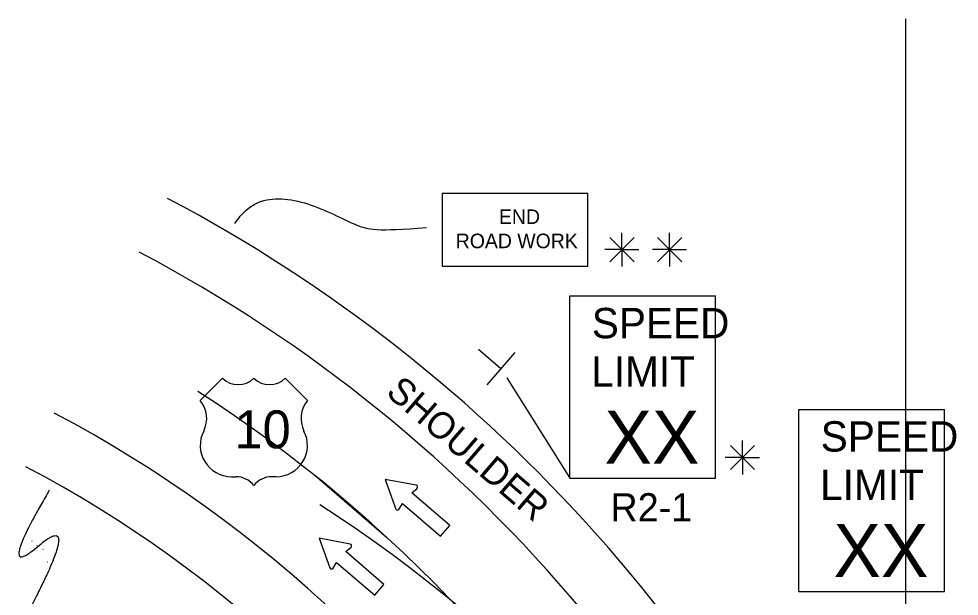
# Model space of a CAD drawing. Extents: x 16729 to 18464, y 5737 to 6974.
# Drawn here: x 16747 to 16994.8, y 6821.9 to 6974.1 of the extents above; entities that cross this region are included whole.
import ezdxf

# ---------------------------------------------------------------- set-up
doc = ezdxf.new("R2010")
doc.units = 0
for name, color, linetype in [('ALI_LEGAL_EX', 7, 'Continuous'), ('MT_SCRATCH_LEVEL_E', 7, 'Continuous'), ('PAVT_EDGE_EX', 7, 'Continuous'), ('TRAFFIC_SIGNS_PR', 7, 'Continuous'), ('TYPICAL_EX', 7, 'Continuous'), ('TYPICAL_TEXT_DIMEN_PR', 7, 'Continuous')]:
    doc.layers.add(name, color=color, linetype=linetype)

msp = doc.modelspace()

# ---------------------------------------------------------------- linework, layer by layer
at = {"layer": 'ALI_LEGAL_EX'}
for p, q in [((16980.68, 6974.12), (16980.68, 6155.98)), ((16980.68, 6891.53), (16980.68, 6027.61))]:
    msp.add_line(p, q, dxfattribs=at)
msp.add_lwpolyline([(16843.92, 6837.36), (16824.97, 6853.66)], dxfattribs=at)
for centre in [(16597.51, 6569.52), (16629.65, 6539.64)]:
    msp.add_arc(centre, 364, 0, 57.2958, dxfattribs=at)
at = {"layer": 'MT_SCRATCH_LEVEL_E'}
for p, q in [((16851.73, 6851.09), (16843.54, 6852.67)), ((16843.54, 6852.67), (16846.35, 6844.83)), ((16850.54, 6849.14), (16851.94, 6850.28)), ((16860.59, 6840.5), (16850.54, 6849.14)), ((16847.18, 6844.75), (16848.1, 6846.31)), ((16848.1, 6846.31), (16858.15, 6837.66)), ((16858.15, 6837.66), (16860.59, 6840.5)), ((16834.35, 6835.57), (16826.16, 6837.15)), ((16826.16, 6837.15), (16828.97, 6829.31)), ((16833.16, 6833.62), (16834.56, 6834.76)), ((16843.21, 6824.97), (16833.16, 6833.62)), ((16829.8, 6829.23), (16830.72, 6830.78)), ((16830.72, 6830.78), (16840.77, 6822.14)), ((16840.77, 6822.14), (16843.21, 6824.97))]:
    msp.add_line(p, q, dxfattribs=at)
for centre, start, end in [((16851.63, 6850.64), 309.3361, 79.073), ((16846.78, 6845), 199.7248, 329.2637), ((16834.25, 6835.11), 309.3361, 79.073), ((16829.4, 6829.47), 199.7248, 329.2637)]:
    msp.add_arc(centre, 0.463, start, end, dxfattribs=at)
at = {"layer": 'PAVT_EDGE_EX'}
for centre, radius, start, end in [((16597.51, 6569.52), 404, 21.0961, 62.1564), ((16597.51, 6569.52), 388, 17.5132, 62.1564), ((17325.51, 6569.52), 380, 123.7854, 157.5011), ((17325.51, 6569.52), 364, 123.7854, 165.0045), ((16597.51, 6569.52), 340, 0, 62.1564), ((16597.51, 6569.52), 324, 0, 62.1564)]:
    msp.add_arc(centre, radius, start, end, dxfattribs=at)
at = {"layer": 'TRAFFIC_SIGNS_PR'}
for p, q in [((16892.23, 6901.02), (16930.63, 6901.02)), ((16892.23, 6853.02), (16892.23, 6901.02)), ((16930.63, 6853.02), (16930.63, 6901.02)), ((16952.57, 6871.13), (16990.97, 6871.13)), ((16952.57, 6823.13), (16952.57, 6871.13)), ((16990.97, 6823.13), (16990.97, 6871.13)), ((16892.23, 6853.02), (16930.63, 6853.02)), ((16952.57, 6823.13), (16990.97, 6823.13))]:
    msp.add_line(p, q, dxfattribs=at)
msp.add_lwpolyline([(16858.53, 6908.89), (16896.93, 6908.89), (16896.93, 6928.09), (16858.53, 6928.09)], close=True, dxfattribs=at)
at = {"layer": 'TYPICAL_EX'}
for p, q in [((16794.78, 6873.43), (16800.67, 6879.32)), ((16823.07, 6873.43), (16817.18, 6879.32)), ((16803.02, 6853.37), (16804.2, 6853.37)), ((16814.83, 6853.37), (16813.65, 6853.37))]:
    msp.add_line(p, q, dxfattribs=at)
for centre, radius, start, end in [((16804.8, 6883.62), 5.96, 226.1404, 313.8596), ((16813.05, 6883.62), 5.96, 226.1404, 313.8596), ((16789.19, 6868.71), 7.31, 333.0977, 40.1936), ((16828.66, 6868.71), 7.31, 139.8064, 206.9023), ((16803.03, 6861.61), 8.24, 152.6698, 269.9013), ((16814.81, 6861.61), 8.24, 270.0987, 27.3302), ((16804.21, 6847.46), 5.91, 37.1038, 90.1385), ((16813.63, 6847.46), 5.91, 89.8615, 142.8962)]:
    msp.add_arc(centre, radius, start, end, dxfattribs=at)
at = {"layer": 'TYPICAL_TEXT_DIMEN_PR'}
for p, q in [((16902.77, 6916.45), (16909.14, 6910.07)), ((16909.14, 6916.45), (16902.77, 6910.07)), ((16905.96, 6913.26), (16905.96, 6917.72)), ((16921.7, 6916.45), (16915.32, 6910.07)), ((16915.33, 6916.45), (16921.7, 6910.07)), ((16918.51, 6913.26), (16918.51, 6917.72)), ((16905.96, 6913.26), (16901.42, 6913.26)), ((16905.96, 6913.26), (16909.14, 6913.26)), ((16905.96, 6913.26), (16910.43, 6913.26)), ((16905.96, 6913.26), (16905.96, 6908.76)), ((16918.51, 6913.26), (16913.98, 6913.26)), ((16918.51, 6913.26), (16921.7, 6913.26)), ((16918.51, 6913.26), (16922.99, 6913.26)), ((16918.51, 6913.26), (16918.51, 6908.76)), ((16874.03, 6881.81), (16868.13, 6886.89)), ((16877.7, 6886.08), (16870.36, 6877.55)), ((16875.6, 6879.48), (16892.23, 6853.02)), ((16934.54, 6861.63), (16940.91, 6855.25)), ((16940.91, 6861.63), (16934.54, 6855.25)), ((16937.72, 6858.44), (16937.72, 6862.9)), ((16937.72, 6858.44), (16933.19, 6858.44)), ((16937.72, 6858.44), (16940.91, 6858.44)), ((16937.72, 6858.44), (16942.2, 6858.44)), ((16937.72, 6858.44), (16937.72, 6853.94)), ((16755, 6849.79), (16755, 6849.79)), ((16755, 6849.79), (16755, 6849.79)), ((16753.21, 6846.62), (16753.21, 6846.62)), ((16753.21, 6846.62), (16753.21, 6846.62)), ((16754.09, 6848.22), (16754.09, 6848.22)), ((16754.09, 6848.22), (16754.09, 6848.22)), ((16752.37, 6845.01), (16752.37, 6845.01)), ((16752.37, 6845.01), (16752.37, 6845.01)), ((16750.89, 6841.69), (16750.89, 6841.69)), ((16750.89, 6841.69), (16750.89, 6841.69)), ((16751.59, 6843.37), (16751.59, 6843.36)), ((16751.59, 6843.37), (16751.59, 6843.36)), ((16750.33, 6839.95), (16750.33, 6839.95)), ((16750.33, 6839.95), (16750.33, 6839.95)), ((16750.05, 6838.15), (16750.07, 6838.15)), ((16750.05, 6838.15), (16750.07, 6838.15)), ((16750.48, 6836.39), (16750.51, 6836.41)), ((16750.48, 6836.39), (16750.51, 6836.41)), ((16751.83, 6835.17), (16751.84, 6835.18)), ((16751.83, 6835.17), (16751.84, 6835.18)), ((16753.36, 6834.17), (16753.34, 6834.15)), ((16753.36, 6834.17), (16753.34, 6834.15)), ((16754.39, 6832.67), (16754.36, 6832.66)), ((16754.39, 6832.67), (16754.36, 6832.66)), ((16754.31, 6829.06), (16754.3, 6829.06)), ((16754.31, 6829.06), (16754.3, 6829.06)), ((16754.58, 6830.86), (16754.57, 6830.86)), ((16754.58, 6830.86), (16754.57, 6830.86)), ((16753.81, 6827.31), (16753.81, 6827.31)), ((16753.81, 6827.31), (16753.81, 6827.31)), ((16752.49, 6823.92), (16752.49, 6823.92)), ((16752.49, 6823.92), (16752.49, 6823.92)), ((16753.19, 6825.6), (16753.19, 6825.6)), ((16753.19, 6825.6), (16753.19, 6825.6)), ((16751.73, 6822.26), (16751.73, 6822.27)), ((16751.73, 6822.26), (16751.73, 6822.27))]:
    msp.add_line(p, q, dxfattribs=at)
for points, degree in [([(16803.94, 6920.13), (16804.68, 6921.24), (16808.91, 6927.57), (16823.23, 6926.36), (16836.9, 6918.75), (16841.37, 6918.06), (16854.42, 6919.1)], 3), ([(16755, 6849.79), (16740.54, 6825.17), (16763.75, 6845.02), (16750.1, 6819.01)], 2)]:
    msp.add_open_spline(points, degree=degree, dxfattribs=at)

# ---------------------------------------------------------------- texts
at = {"layer": 'TRAFFIC_SIGNS_PR'}
for s, height, p in [('END', 3.831, (16873.53, 6920.02)), ('ROAD WORK', 3.831, (16862.14, 6913.63)), ('SPEED', 8, (16898, 6889.88)), ('LIMIT', 8, (16897.84, 6877.08)), ('XX', 14.031, (16901.34, 6856.78)), ('SPEED', 8, (16958.34, 6859.99)), ('LIMIT', 8, (16958.18, 6847.19)), ('R2-1', 7.44, (16902.91, 6841.58)), ('XX', 14.031, (16961.69, 6826.89))]:
    msp.add_text(s, height=height, dxfattribs=at).set_placement(p)
at = {"layer": 'TYPICAL_EX'}
msp.add_text('10', height=10, dxfattribs=at).set_placement((16803.77, 6860.85))
at = {"layer": 'TYPICAL_TEXT_DIMEN_PR'}
msp.add_text('SHOULDER', height=7, rotation=319.2839, dxfattribs=at).set_placement((16843.44, 6875.12))

doc.saveas('drawing.dxf')
